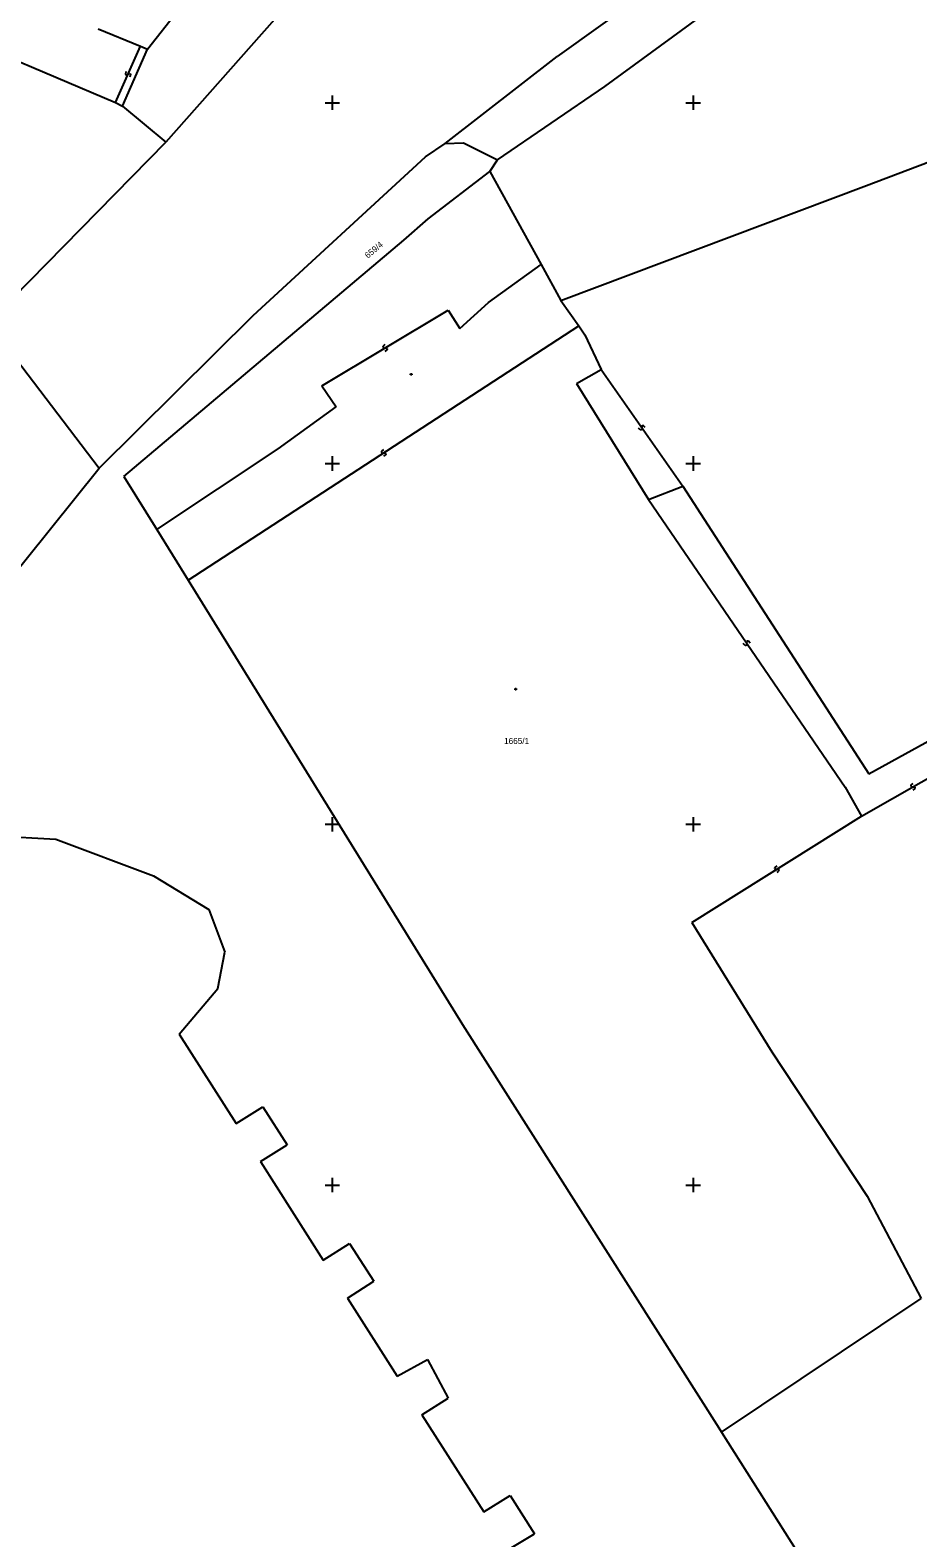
# Model space of a CAD drawing. Extents: x -492811 to -492366, y -1127107 to -1126748.
# Drawn here: x -492596.7 to -492547.5, y -1127059.6 to -1126976 of the extents above; entities that cross this region are included whole.
import ezdxf

# ---------------------------------------------------------------- set-up
doc = ezdxf.new("R2010")
doc.units = 0
doc.layers.add('katastrální mapa', color=7, linetype='Continuous')
doc.layers.add('síť', color=7, linetype='Continuous')

msp = doc.modelspace()

# ---------------------------------------------------------------- linework, layer by layer
at = {"layer": 'katastrální mapa'}
for p, q in [((-492549.77, -1126964.67), (-492567.53, -1126977.44)), ((-492564.89, -1126979.09), (-492544.76, -1126964.37)), ((-492578.95, -1126970.57), (-492589.22, -1126982.18)), ((-492590.24, -1126977.02), (-492588.53, -1126974.85)), ((-492602.96, -1126975.34), (-492592.02, -1126979.99)), ((-492592.98, -1126975.9), (-492590.64, -1126976.86)), ((-492592.02, -1126979.99), (-492590.64, -1126976.86)), ((-492591.62, -1126980.19), (-492590.24, -1126977.02)), ((-492590.64, -1126976.86), (-492590.24, -1126977.02)), ((-492573.74, -1126982.26), (-492567.53, -1126977.44)), ((-492591.44, -1126978.27), (-492591.47, -1126978.41)), ((-492591.47, -1126978.41), (-492591.45, -1126978.46)), ((-492591.45, -1126978.46), (-492591.42, -1126978.47)), ((-492591.42, -1126978.47), (-492591.36, -1126978.45)), ((-492591.36, -1126978.45), (-492591.3, -1126978.4)), ((-492591.3, -1126978.4), (-492591.24, -1126978.38)), ((-492591.24, -1126978.38), (-492591.21, -1126978.39)), ((-492591.19, -1126978.44), (-492591.22, -1126978.58)), ((-492591.21, -1126978.39), (-492591.19, -1126978.44)), ((-492570.84, -1126983.17), (-492564.89, -1126979.09)), ((-492592.02, -1126979.99), (-492591.62, -1126980.19)), ((-492591.62, -1126980.19), (-492589.22, -1126982.18)), ((-492599.05, -1126992.2), (-492589.22, -1126982.18)), ((-492574.83, -1126983), (-492573.74, -1126982.26)), ((-492573.74, -1126982.26), (-492572.72, -1126982.22)), ((-492572.72, -1126982.22), (-492570.84, -1126983.17)), ((-492584.38, -1126991.8), (-492574.83, -1126983)), ((-492571.26, -1126983.81), (-492570.84, -1126983.17)), ((-492574.68, -1126986.44), (-492571.26, -1126983.81)), ((-492571.26, -1126983.81), (-492568.43, -1126988.97)), ((-492576.04, -1126987.61), (-492574.68, -1126986.44)), ((-492591.55, -1127000.71), (-492576.04, -1126987.61)), ((-492571.34, -1126991.08), (-492568.43, -1126988.97)), ((-492568.43, -1126988.97), (-492567.33, -1126990.97)), ((-492567.33, -1126990.97), (-492566.33, -1126992.36)), ((-492592.92, -1127000.25), (-492584.38, -1126991.8)), ((-492580.58, -1126995.69), (-492573.58, -1126991.5)), ((-492573.58, -1126991.5), (-492572.94, -1126992.52)), ((-492572.94, -1126992.52), (-492571.34, -1126991.08)), ((-492587.99, -1127006.47), (-492566.33, -1126992.36)), ((-492566.33, -1126992.36), (-492566, -1126992.87)), ((-492577.19, -1126993.5), (-492577.2, -1126993.55)), ((-492577.2, -1126993.55), (-492577.18, -1126993.58)), ((-492577.08, -1126993.41), (-492577.19, -1126993.5)), ((-492566, -1126992.87), (-492565.1, -1126994.78)), ((-492597.85, -1126993.77), (-492592.92, -1127000.25)), ((-492577.18, -1126993.58), (-492577.12, -1126993.6)), ((-492577.12, -1126993.6), (-492577.04, -1126993.59)), ((-492576.97, -1126993.69), (-492577.08, -1126993.78)), ((-492577.04, -1126993.59), (-492576.98, -1126993.61)), ((-492576.98, -1126993.61), (-492576.96, -1126993.64)), ((-492576.96, -1126993.64), (-492576.97, -1126993.69)), ((-492575.66, -1126995.03), (-492575.6, -1126995.03)), ((-492575.66, -1126995.09), (-492575.66, -1126995.03)), ((-492575.6, -1126995.09), (-492575.66, -1126995.09)), ((-492575.6, -1126995.03), (-492575.6, -1126995.09)), ((-492566.46, -1126995.56), (-492565.1, -1126994.78)), ((-492565.1, -1126994.78), (-492560.58, -1127001.26)), ((-492580.58, -1126995.69), (-492579.79, -1126996.86)), ((-492566.46, -1126995.56), (-492562.48, -1127001.99)), ((-492583.01, -1126999.18), (-492579.79, -1126996.86)), ((-492562.93, -1126998.13), (-492563.03, -1126998.03)), ((-492562.88, -1126998.14), (-492562.93, -1126998.13)), ((-492562.84, -1126998.12), (-492562.88, -1126998.14)), ((-492562.84, -1126997.92), (-492562.85, -1126997.98)), ((-492562.85, -1126997.98), (-492562.83, -1126998.06)), ((-492562.8, -1126997.9), (-492562.84, -1126997.92)), ((-492562.83, -1126998.06), (-492562.84, -1126998.12)), ((-492562.75, -1126997.91), (-492562.8, -1126997.9)), ((-492562.65, -1126998.01), (-492562.75, -1126997.91)), ((-492589.73, -1127003.65), (-492583.01, -1126999.18)), ((-492577.27, -1126999.32), (-492577.28, -1126999.37)), ((-492577.28, -1126999.37), (-492577.26, -1126999.41)), ((-492577.16, -1126999.23), (-492577.27, -1126999.32)), ((-492577.26, -1126999.41), (-492577.2, -1126999.42)), ((-492577.2, -1126999.42), (-492577.12, -1126999.41)), ((-492577.05, -1126999.51), (-492577.16, -1126999.6)), ((-492577.12, -1126999.41), (-492577.06, -1126999.42)), ((-492577.06, -1126999.42), (-492577.04, -1126999.46)), ((-492577.04, -1126999.46), (-492577.05, -1126999.51)), ((-492598.31, -1127006.99), (-492592.92, -1127000.25)), ((-492591.55, -1127000.71), (-492589.73, -1127003.65)), ((-492562.48, -1127001.99), (-492560.58, -1127001.26)), ((-492560.58, -1127001.26), (-492550.27, -1127017.21)), ((-492562.48, -1127001.99), (-492551.58, -1127017.94)), ((-492589.73, -1127003.65), (-492587.99, -1127006.47)), ((-492587.99, -1127006.47), (-492572.78, -1127031.1)), ((-492557.12, -1127010.08), (-492557.22, -1127009.97)), ((-492557.07, -1127010.09), (-492557.12, -1127010.08)), ((-492557.03, -1127010.06), (-492557.07, -1127010.09)), ((-492557.03, -1127009.87), (-492557.04, -1127009.92)), ((-492557.04, -1127009.92), (-492557.02, -1127010.01)), ((-492556.99, -1127009.84), (-492557.03, -1127009.87)), ((-492557.02, -1127010.01), (-492557.03, -1127010.06)), ((-492556.94, -1127009.85), (-492556.99, -1127009.84)), ((-492556.84, -1127009.96), (-492556.94, -1127009.85)), ((-492569.86, -1127012.48), (-492569.8, -1127012.48)), ((-492569.86, -1127012.54), (-492569.86, -1127012.48)), ((-492569.8, -1127012.54), (-492569.86, -1127012.54)), ((-492569.8, -1127012.48), (-492569.8, -1127012.54)), ((-492550.27, -1127017.21), (-492545.86, -1127014.78)), ((-492550.66, -1127019.54), (-492544.99, -1127016.3)), ((-492547.82, -1127017.73), (-492547.93, -1127017.82)), ((-492551.58, -1127017.94), (-492550.66, -1127019.54)), ((-492547.93, -1127017.82), (-492547.94, -1127017.87)), ((-492547.94, -1127017.87), (-492547.92, -1127017.91)), ((-492547.92, -1127017.91), (-492547.87, -1127017.92)), ((-492547.87, -1127017.92), (-492547.78, -1127017.92)), ((-492547.72, -1127018.02), (-492547.83, -1127018.11)), ((-492547.78, -1127017.92), (-492547.73, -1127017.93)), ((-492547.73, -1127017.93), (-492547.71, -1127017.97)), ((-492547.71, -1127017.97), (-492547.72, -1127018.02)), ((-492560.08, -1127025.44), (-492550.66, -1127019.54)), ((-492601.18, -1127020.51), (-492595.33, -1127020.82)), ((-492595.33, -1127020.82), (-492589.91, -1127022.85)), ((-492555.48, -1127022.39), (-492555.49, -1127022.45)), ((-492555.49, -1127022.45), (-492555.47, -1127022.48)), ((-492555.37, -1127022.3), (-492555.48, -1127022.39)), ((-492555.47, -1127022.48), (-492555.41, -1127022.49)), ((-492555.41, -1127022.49), (-492555.33, -1127022.49)), ((-492555.26, -1127022.59), (-492555.37, -1127022.68)), ((-492555.33, -1127022.49), (-492555.27, -1127022.5)), ((-492555.27, -1127022.5), (-492555.25, -1127022.53)), ((-492555.25, -1127022.53), (-492555.26, -1127022.59)), ((-492589.91, -1127022.85), (-492586.85, -1127024.73)), ((-492586.85, -1127024.73), (-492585.95, -1127027.08)), ((-492560.08, -1127025.44), (-492555.64, -1127032.62)), ((-492586.34, -1127029.1), (-492585.95, -1127027.08)), ((-492588.48, -1127031.63), (-492586.34, -1127029.1)), ((-492572.78, -1127031.1), (-492566.38, -1127041.18)), ((-492588.48, -1127031.63), (-492585.32, -1127036.59)), ((-492555.64, -1127032.62), (-492550.36, -1127040.62)), ((-492585.32, -1127036.59), (-492583.85, -1127035.66)), ((-492583.85, -1127035.66), (-492582.51, -1127037.76)), ((-492583.98, -1127038.69), (-492582.51, -1127037.76)), ((-492583.98, -1127038.69), (-492580.5, -1127044.16)), ((-492566.38, -1127041.18), (-492561.95, -1127048.14)), ((-492550.36, -1127040.62), (-492547.36, -1127046.29)), ((-492580.5, -1127044.16), (-492579.04, -1127043.23)), ((-492579.04, -1127043.23), (-492577.7, -1127045.33)), ((-492579.16, -1127046.26), (-492577.7, -1127045.33)), ((-492579.16, -1127046.26), (-492576.4, -1127050.6)), ((-492558.42, -1127053.7), (-492547.36, -1127046.29)), ((-492561.95, -1127048.14), (-492558.58, -1127053.45)), ((-492576.4, -1127050.6), (-492574.73, -1127049.66)), ((-492574.73, -1127049.66), (-492573.57, -1127051.81)), ((-492575.04, -1127052.74), (-492573.57, -1127051.81)), ((-492575.04, -1127052.74), (-492571.61, -1127058.12)), ((-492558.58, -1127053.45), (-492558.42, -1127053.7)), ((-492558.42, -1127053.7), (-492538.02, -1127085.93)), ((-492571.61, -1127058.12), (-492570.15, -1127057.2)), ((-492570.15, -1127057.2), (-492568.79, -1127059.34)), ((-492570.27, -1127060.22), (-492568.79, -1127059.34))]:
    msp.add_line(p, q, dxfattribs=at)
msp.add_lwpolyline([(-492567.33, -1126990.97), (-492550.39, -1126984.58), (-492539.32, -1126980.4)], dxfattribs=at)
at = {"layer": 'síť'}
for p, q in [((-492580.4, -1126980), (-492579.6, -1126980)), ((-492580, -1126979.6), (-492580, -1126980.4)), ((-492560.4, -1126980), (-492559.6, -1126980)), ((-492560, -1126979.6), (-492560, -1126980.4)), ((-492580.4, -1127000), (-492579.6, -1127000)), ((-492580, -1126999.6), (-492580, -1127000.4)), ((-492560.4, -1127000), (-492559.6, -1127000)), ((-492560, -1126999.6), (-492560, -1127000.4)), ((-492580.4, -1127020), (-492579.6, -1127020)), ((-492580, -1127019.6), (-492580, -1127020.4)), ((-492560.4, -1127020), (-492559.6, -1127020)), ((-492560, -1127019.6), (-492560, -1127020.4)), ((-492580.4, -1127040), (-492579.6, -1127040)), ((-492580, -1127039.6), (-492580, -1127040.4)), ((-492560.4, -1127040), (-492559.6, -1127040)), ((-492560, -1127039.6), (-492560, -1127040.4))]:
    msp.add_line(p, q, dxfattribs=at)

# ---------------------------------------------------------------- texts
at = {"layer": 'katastrální mapa'}
msp.add_text('659/4', height=0.34, rotation=39.591, dxfattribs=at).set_placement((-492578.03, -1126988.65))
msp.add_text('1665/1', height=0.34, dxfattribs=at).set_placement((-492570.48, -1127015.55))

doc.saveas('drawing.dxf')
